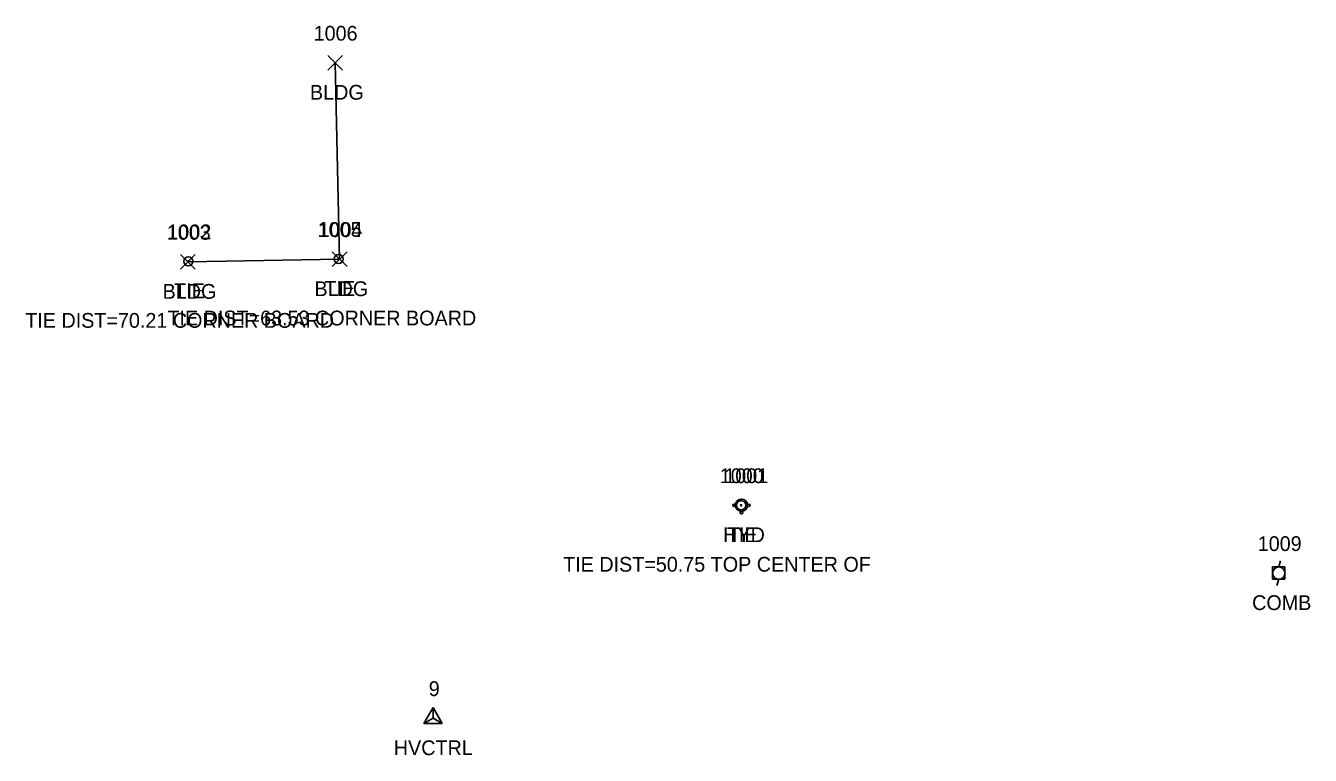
# Model space of a CAD drawing. Extents: x 1653908 to 1654393, y 539913 to 544256.
# Drawn here: x 1653943.5 to 1654117.5, y 540776.4 to 540875.3 of the extents above; entities that cross this region are included whole.
import ezdxf

# ---------------------------------------------------------------- set-up
doc = ezdxf.new("R2010")
doc.units = 0
for name, color, linetype in [('C_A', 7, 'Continuous'), ('C_C', 7, 'Continuous'), ('C_I', 7, 'Continuous'), ('CBP', 7, 'Continuous'), ('CPSM', 7, 'Continuous'), ('L_A', 7, 'Continuous'), ('L_I', 7, 'Continuous'), ('L_TIC', 7, 'Continuous'), ('LBC', 7, 'Continuous'), ('U_A', 7, 'Continuous'), ('U_I', 7, 'Continuous'), ('UP', 7, 'Continuous'), ('UWFH', 7, 'Continuous')]:
    doc.layers.add(name, color=color, linetype=linetype)

msp = doc.modelspace()

# ---------------------------------------------------------------- linework, layer by layer
at = {"layer": 'CBP'}
for centre, radius in [((1653985.88, 540843.7), 0.625), ((1653965.52, 540843.38), 0.625), ((1653965.52, 540843.38), 0.0833), ((1653985.88, 540843.7), 0.0833), ((1654040.4, 540810.33), 0.625), ((1654040.4, 540810.33), 0.0833)]:
    msp.add_circle(centre, radius, dxfattribs=at)
at = {"layer": 'CPSM'}
for p, q in [((1653997.41, 540780.75), (1653998.66, 540782.92)), ((1653999.91, 540780.75), (1653998.66, 540782.92)), ((1653998.66, 540781.47), (1653998.66, 540782.92)), ((1653997.41, 540780.75), (1653998.66, 540781.47)), ((1653997.41, 540780.75), (1653999.91, 540780.75)), ((1653998.66, 540781.47), (1653998.66, 540781.47)), ((1653998.66, 540781.47), (1653999.91, 540780.75))]:
    msp.add_line(p, q, dxfattribs=at)
at = {"layer": 'L_TIC'}
for points in [[(1653984.4, 540869.29), (1653986.4, 540871.29)], [(1653986.4, 540869.29), (1653984.4, 540871.29)], [(1653985.01, 540842.67), (1653987.01, 540844.67)], [(1653987.01, 540842.67), (1653985.01, 540844.67)], [(1653964.44, 540842.31), (1653966.44, 540844.31)], [(1653966.44, 540842.31), (1653964.44, 540844.31)]]:
    msp.add_lwpolyline(points, dxfattribs=at)
at = {"layer": 'LBC'}
msp.add_lwpolyline([(1653965.44, 540843.31), (1653986.01, 540843.67), (1653985.4, 540870.29)], dxfattribs=at)
at = {"layer": 'UP'}
for p, q in [((1654113.49, 540802.8), (1654113.24, 540801.97)), ((1654112.41, 540800.3), (1654112.41, 540801.97)), ((1654112.41, 540801.97), (1654114.08, 540801.97)), ((1654113.24, 540801.13), (1654113.24, 540801.13)), ((1654114.08, 540801.97), (1654114.08, 540800.3)), ((1654114.08, 540800.3), (1654112.41, 540800.3)), ((1654112.99, 540799.47), (1654113.24, 540800.3))]:
    msp.add_line(p, q, dxfattribs=at)
msp.add_circle((1654113.24, 540801.13), 0.833, dxfattribs=at)
at = {"layer": 'UWFH'}
msp.add_line((1654040.45, 540810.33), (1654040.45, 540810.33), dxfattribs=at)
for centre, radius in [((1654039.45, 540810.33), 0.167), ((1654040.45, 540810.33), 0.833), ((1654041.45, 540810.33), 0.167), ((1654040.45, 540809.33), 0.167)]:
    msp.add_circle(centre, radius, dxfattribs=at)

# ---------------------------------------------------------------- texts
at = {"layer": 'C_A'}
for s, p in [('TIE', (1653963.6, 540838.38)), ('TIE', (1653983.96, 540838.7)), ('TIE', (1654038.48, 540805.33)), ('HVCTRL', (1653993.35, 540776.47))]:
    msp.add_text(s, height=2, dxfattribs=at).set_placement(p)
at = {"layer": 'C_C'}
for s, p in [('TIE DIST=70.21 CORNER BOARD', (1653943.42, 540834.38)), ('TIE DIST=63.53 CORNER BOARD', (1653962.68, 540834.7)), ('TIE DIST=50.75 TOP CENTER OF', (1654016.29, 540801.33))]:
    msp.add_text(s, height=2, dxfattribs=at).set_placement(p)
at = {"layer": 'C_I'}
for s, p in [('1002', (1653962.67, 540846.38)), ('1005', (1653983.03, 540846.7)), ('1001', (1654038.12, 540813.33)), ('9', (1653998.08, 540784.47))]:
    msp.add_text(s, height=2, dxfattribs=at).set_placement(p)
at = {"layer": 'L_A'}
for p in [(1653981.99, 540865.29), (1653962.03, 540838.31), (1653982.6, 540838.67)]:
    msp.add_text('BLDG', height=2, dxfattribs=at).set_placement(p)
at = {"layer": 'L_I'}
for s, p in [('1006', (1653982.49, 540873.29)), ('1003', (1653962.59, 540846.31)), ('1004', (1653983.16, 540846.67))]:
    msp.add_text(s, height=2, dxfattribs=at).set_placement(p)
at = {"layer": 'U_A'}
for s, p in [('HYD', (1654037.97, 540805.33)), ('COMB', (1654109.63, 540796.13))]:
    msp.add_text(s, height=2, dxfattribs=at).set_placement(p)
at = {"layer": 'U_I'}
for s, p in [('1000', (1654037.51, 540813.33)), ('1009', (1654110.39, 540804.13))]:
    msp.add_text(s, height=2, dxfattribs=at).set_placement(p)

doc.saveas('drawing.dxf')
